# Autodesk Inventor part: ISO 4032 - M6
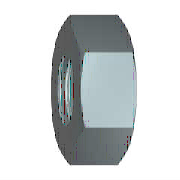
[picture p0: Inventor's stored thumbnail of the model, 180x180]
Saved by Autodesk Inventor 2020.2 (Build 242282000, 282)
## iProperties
Manager: www.cadconsulting.pl
Company: Fabian Stasiak CAD Consulting
Created: 2010-02
Part Number: ISO 4032 - M6
Material: Stal nierdzewna, 440C
Description: Nakrętki sześciokątne, styl 1 - Klasa dokładności A i B
Document SubType Name: Modeling
Standard: ISO 4032
Designer: F.Stasiak
Standard Revision: Third edition 1999-08-15
Standards Organization: ISO
Language: pl-PL
Size Designation: M6
Categories: <MemberInstance><Categories><Category DisplayName="Mocowania" InternalName="e4da775c-781d-43d5-af7c-5136215cf5a6" Mnemonic="FSTN"><Category DisplayName="Nakrętk
Density: 7.75 g/cm^3
Appearance: Metal-Stal
IsCustomPart: 0
Author: F.Stasiak
Subject: Zbiór ćwiczeń. Autodesk Inventor 2020. Kurs podstawowy
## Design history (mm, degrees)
sketch "Sketch1"
  geometry: L1 (-5.774, 0)-(-2.887, 5); L2 (-2.887, 5)-(2.887, 5); L3 (2.887, 5)-(5.774, 0); L4 (5.774, 0)-(2.887, -5); L5 (2.887, -5)-(-2.887, -5); L6 (-2.887, -5)-(-5.774, 0); 2 further points
  constraints: 12 end point, 1 coincident, 1 horizontal, 11 other
  dimensions: "d0" = 11.54701 distance of L3.end L1.start (= 1.1547 x SW)
extrude "Body" new body sketch "Sketch1" distance "d1" = 5.2 (= KOH); taper "d2" = 0 deg
sketch "Sketch2"
  geometry: L1 (0, 2.887)-(0, 5.774) reference; L2 (0, 5.774)-(5.2, 5.774) reference; L3 (5.2, 2.887)-(5.2, 5.774) reference; L4 (-1.04, 0)-(6.24, 0) reference; L5 (0.764, 5.774)-(0, 4.45); L6 (4.436, 5.774)-(5.2, 4.45)
  constraints: 4 end point, 4 point on line
  dimensions: "d3" = 30 deg angle of L1 L5 (= ANG1); "d4" = 30 deg angle of L3 L6 (= ANG2); "d5" = 8.9 diameter of L5.end L4 (= SW0); "d6" = 8.9 diameter of L6.end L4 (= SW01)
revolve "Chamfer1" sketch "Sketch2" stored, may be unused: angle "d7" = 90 deg
sketch "Sketch3"
  geometry: 4 further points
  constraints: 1 coincident, 1 other
hole "Thread" sketch "Sketch3" at (0, 0) diameter "d25" = 4.917; stored, may be unused: countersink angle "d29" = 82 deg, drill point angle "d31" = 118 deg; dims "d26" = 6, "d27" = 4, "d28" = 2, "d30" = 8
chamfer "Chamfer2" distance "d8" = 0.54127 (= -0.5 x GD1 + 0.5 x NND); stored, may be unused: angle "d9" = 30 deg, second distance "d40" = 0.54127 (= -0.5 x GD1 + 0.5 x NND)
chamfer "Chamfer3" distance "d10" = 0.54127 (= -0.5 x GD1 + 0.5 x NND); stored, may be unused: angle "d11" = 30 deg, second distance "d41" = 0.54127 (= -0.5 x GD1 + 0.5 x NND)
workaxis "Work Axis1"
workplane "Work Plane1"
body "Solid1"
other parameters: "ANG1" = 30 deg [user parameter; used in 1 equation term], "ANG2" = 30 deg [user parameter; used in 1 equation term], "NND" = 6 [user parameter; used in 4 equation terms], "KOH" = 5.2 [user parameter; used in 1 equation term], "SW0" = 8.9 [user parameter; used in 2 equation terms], "SW01" = 8.9 (= SW0) [user parameter; used in 1 equation term], "GD1" = 4.91747 (computed from THREADDIA, PTC, TOA) [user parameter; used in 4 equation terms], "d13" = 0, "d14" = 0, "d39" = 0, "d42" = 0, "GUL" = 0.54127 (= 0.541266 x PTC) [user parameter], "THREADDIA" = 6 [user parameter; used in 1 equation term], "TOA" = 30 deg [user parameter; used in 1 equation term], "PTC" = 1 [user parameter; used in 4 equation terms], "E0" = 11.55 (= 1.155 x SW) [user parameter], "GAL" = 0.54127 (= 0.541266 x PTC) [user parameter]
